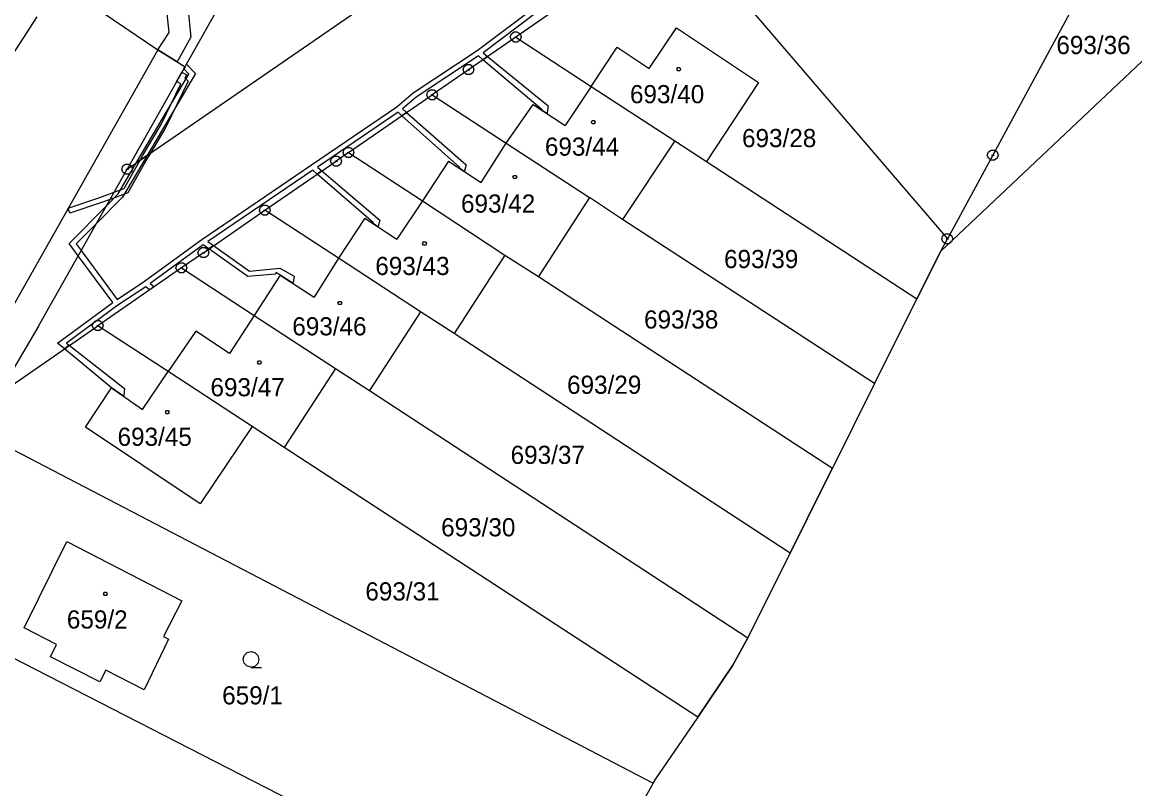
# Model space of a CAD drawing. Extents: x -759699 to -757730, y -1172308 to -1170857.
# Drawn here: x -758375.4 to -758271.3, y -1171278.3 to -1171206.6 of the extents above; entities that cross this region are included whole.
import ezdxf

# ---------------------------------------------------------------- set-up
doc = ezdxf.new("R2010")
doc.units = 0
for name, color, linetype in [('Vrstva 1', 7, 'Continuous'), ('Vrstva 11', 7, 'Continuous'), ('Vrstva 12', 7, 'Continuous'), ('Vrstva 13', 7, 'Continuous'), ('Vrstva 2', 7, 'Continuous'), ('Vrstva 3', 7, 'Continuous'), ('Vrstva 4', 7, 'Continuous'), ('Vrstva 5', 7, 'Continuous'), ('Vrstva 8', 7, 'Continuous')]:
    doc.layers.add(name, color=color, linetype=linetype)

msp = doc.modelspace()

# ---------------------------------------------------------------- linework, layer by layer
at = {"layer": 'Vrstva 1'}
for p, q in [((-758386.86, -1171192.81), (-758362.75, -1171209.16)), ((-758365.62, -1171220.33), (-758328.98, -1171195.04)), ((-758274.38, -1171200.21), (-758284.58, -1171219.02)), ((-758360.06, -1171210.49), (-758355.37, -1171202.2)), ((-758323.19, -1171203.79), (-758329.24, -1171207.97)), ((-758306.89, -1171205.79), (-758288.83, -1171226.85)), ((-758374.07, -1171206.07), (-758380.71, -1171216.2)), ((-758316.74, -1171210.9), (-758314.19, -1171207.09)), ((-758314.19, -1171207.09), (-758306.51, -1171212.22)), ((-758329.24, -1171207.97), (-758333.65, -1171211.02)), ((-758329.24, -1171207.97), (-758322.18, -1171212.58)), ((-758289.45, -1171228), (-758267.94, -1171207.71)), ((-758362.75, -1171209.16), (-758376.54, -1171233.55)), ((-758362.75, -1171209.16), (-758360.2, -1171210.74)), ((-758322.18, -1171212.58), (-758319.73, -1171208.9)), ((-758319.73, -1171208.9), (-758316.74, -1171210.9)), ((-758360.32, -1171210.95), (-758365.62, -1171220.33)), ((-758360.2, -1171210.74), (-758360.32, -1171210.95)), ((-758360.2, -1171210.74), (-758360.06, -1171210.49)), ((-758333.65, -1171211.02), (-758337.06, -1171213.37)), ((-758306.51, -1171212.22), (-758311.37, -1171219.62)), ((-758322.18, -1171212.58), (-758314.33, -1171217.69)), ((-758344.89, -1171218.77), (-758337.06, -1171213.37)), ((-758337.06, -1171213.37), (-758330.12, -1171217.9)), ((-758330.12, -1171217.9), (-758322.34, -1171222.98)), ((-758314.33, -1171217.69), (-758319.23, -1171225.03)), ((-758314.33, -1171217.69), (-758311.37, -1171219.62)), ((-758352.72, -1171224.17), (-758346.06, -1171219.58)), ((-758344.89, -1171218.77), (-758346.06, -1171219.58)), ((-758344.89, -1171218.77), (-758337.98, -1171223.28)), ((-758284.58, -1171219.02), (-758288.83, -1171226.85)), ((-758373.93, -1171235.02), (-758365.62, -1171220.33)), ((-758311.37, -1171219.62), (-758291.68, -1171232.47)), ((-758337.98, -1171223.28), (-758330.25, -1171228.37)), ((-758322.34, -1171222.98), (-758327.12, -1171230.37)), ((-758319.23, -1171225.03), (-758322.34, -1171222.98)), ((-758358.48, -1171228.15), (-758352.72, -1171224.17)), ((-758345.82, -1171228.67), (-758352.72, -1171224.17)), ((-758295.64, -1171240.4), (-758319.23, -1171225.03)), ((-758289.45, -1171228), (-758288.83, -1171226.85)), ((-758358.48, -1171228.15), (-758360.54, -1171229.57)), ((-758338.14, -1171233.68), (-758345.82, -1171228.67)), ((-758330.25, -1171228.37), (-758335.01, -1171235.72)), ((-758330.25, -1171228.37), (-758327.12, -1171230.37)), ((-758291.68, -1171232.47), (-758289.45, -1171228)), ((-758360.54, -1171229.57), (-758368.37, -1171234.98)), ((-758360.54, -1171229.57), (-758353.72, -1171234.02)), ((-758327.12, -1171230.37), (-758299.59, -1171248.33)), ((-758292.58, -1171234.27), (-758291.68, -1171232.47)), ((-758353.72, -1171234.02), (-758346.1, -1171238.99)), ((-758338.14, -1171233.68), (-758342.93, -1171241.06)), ((-758335.01, -1171235.72), (-758338.14, -1171233.68)), ((-758377.73, -1171241.44), (-758368.37, -1171234.98)), ((-758373.93, -1171235.02), (-758377.73, -1171241.44)), ((-758361.79, -1171239.27), (-758368.37, -1171234.98)), ((-758295.64, -1171240.4), (-758292.58, -1171234.27)), ((-758303.54, -1171256.26), (-758335.01, -1171235.72)), ((-758364.19, -1171242.83), (-758361.79, -1171239.27)), ((-758353.9, -1171244.42), (-758361.79, -1171239.27)), ((-758346.1, -1171238.99), (-758350.91, -1171246.37)), ((-758346.1, -1171238.99), (-758342.93, -1171241.06)), ((-758295.64, -1171240.4), (-758299.59, -1171248.33)), ((-758369.53, -1171244.48), (-758367.09, -1171240.79)), ((-758367.09, -1171240.79), (-758364.19, -1171242.83)), ((-758342.93, -1171241.06), (-758307.5, -1171264.19)), ((-758358.79, -1171251.66), (-758369.53, -1171244.48)), ((-758353.9, -1171244.42), (-758358.79, -1171251.66)), ((-758350.91, -1171246.37), (-758353.9, -1171244.42)), ((-758379.62, -1171244.86), (-758316.38, -1171277.79)), ((-758312.19, -1171271.63), (-758350.91, -1171246.37)), ((-758300.32, -1171249.8), (-758299.59, -1171248.33)), ((-758303.54, -1171256.26), (-758300.32, -1171249.8)), ((-758375.27, -1171263.26), (-758371.28, -1171255.17)), ((-758371.28, -1171255.17), (-758360.49, -1171260.74)), ((-758307.5, -1171264.19), (-758303.54, -1171256.26)), ((-758387.5, -1171260.32), (-758324.71, -1171292.52)), ((-758360.49, -1171260.74), (-758362.21, -1171264.08)), ((-758372.24, -1171264.83), (-758375.27, -1171263.26)), ((-758361.76, -1171264.31), (-758364.03, -1171269.07)), ((-758362.21, -1171264.08), (-758361.76, -1171264.31)), ((-758308.92, -1171266.75), (-758307.5, -1171264.19)), ((-758372.8, -1171265.97), (-758372.24, -1171264.83)), ((-758368.18, -1171268.33), (-758372.8, -1171265.97)), ((-758367.61, -1171267.22), (-758368.18, -1171268.33)), ((-758364.03, -1171269.07), (-758367.61, -1171267.22)), ((-758312.19, -1171271.63), (-758308.92, -1171266.75)), ((-758312.19, -1171271.63), (-758316.16, -1171277.4)), ((-758316.38, -1171277.79), (-758317.68, -1171280.14)), ((-758316.38, -1171277.79), (-758316.16, -1171277.4))]:
    msp.add_line(p, q, dxfattribs=at)
at = {"layer": 'Vrstva 11'}
for p, q in [((-758267.94, -1171207.71), (-758289.45, -1171228)), ((-758289.45, -1171228), (-758291.68, -1171232.47)), ((-758291.68, -1171232.47), (-758292.58, -1171234.27)), ((-758292.58, -1171234.27), (-758295.64, -1171240.4)), ((-758295.64, -1171240.4), (-758299.59, -1171248.33)), ((-758299.59, -1171248.33), (-758300.32, -1171249.8)), ((-758300.32, -1171249.8), (-758303.54, -1171256.26)), ((-758303.54, -1171256.26), (-758307.5, -1171264.19)), ((-758307.5, -1171264.19), (-758308.92, -1171266.75)), ((-758308.92, -1171266.75), (-758312.19, -1171271.63)), ((-758312.19, -1171271.63), (-758316.16, -1171277.4)), ((-758316.38, -1171277.79), (-758317.68, -1171280.14)), ((-758316.16, -1171277.4), (-758316.38, -1171277.79))]:
    msp.add_line(p, q, dxfattribs=at)
at = {"layer": 'Vrstva 12'}
for p, q in [((-758374.07, -1171206.07), (-758380.71, -1171216.2)), ((-758316.74, -1171210.9), (-758314.19, -1171207.09)), ((-758314.19, -1171207.09), (-758306.51, -1171212.22)), ((-758322.18, -1171212.58), (-758319.73, -1171208.9)), ((-758319.73, -1171208.9), (-758316.74, -1171210.9)), ((-758306.51, -1171212.22), (-758311.37, -1171219.62)), ((-758322.18, -1171212.58), (-758324.62, -1171216.25)), ((-758322.18, -1171212.58), (-758314.33, -1171217.69)), ((-758322.18, -1171212.58), (-758314.33, -1171217.69)), ((-758330.12, -1171217.9), (-758327.6, -1171214.27)), ((-758327.6, -1171214.27), (-758324.62, -1171216.25)), ((-758332.47, -1171221.59), (-758330.12, -1171217.9)), ((-758330.12, -1171217.9), (-758322.34, -1171222.98)), ((-758330.12, -1171217.9), (-758322.34, -1171222.98)), ((-758314.33, -1171217.69), (-758319.23, -1171225.03)), ((-758314.33, -1171217.69), (-758311.37, -1171219.62)), ((-758335.52, -1171219.58), (-758337.98, -1171223.28)), ((-758335.52, -1171219.58), (-758332.47, -1171221.59)), ((-758337.98, -1171223.28), (-758340.38, -1171226.89)), ((-758337.98, -1171223.28), (-758330.25, -1171228.37)), ((-758337.98, -1171223.28), (-758330.25, -1171228.37)), ((-758322.34, -1171222.98), (-758327.12, -1171230.37)), ((-758319.23, -1171225.03), (-758322.34, -1171222.98)), ((-758343.38, -1171224.91), (-758345.82, -1171228.67)), ((-758343.38, -1171224.91), (-758340.38, -1171226.89)), ((-758345.82, -1171228.67), (-758348.11, -1171232.3)), ((-758338.14, -1171233.68), (-758345.82, -1171228.67)), ((-758338.14, -1171233.68), (-758345.82, -1171228.67)), ((-758330.25, -1171228.37), (-758335.01, -1171235.72)), ((-758330.25, -1171228.37), (-758327.12, -1171230.37)), ((-758351.28, -1171230.25), (-758353.72, -1171234.02)), ((-758351.28, -1171230.25), (-758348.11, -1171232.3)), ((-758353.72, -1171234.02), (-758356.03, -1171237.57)), ((-758353.72, -1171234.02), (-758346.1, -1171238.99)), ((-758353.72, -1171234.02), (-758346.1, -1171238.99)), ((-758338.14, -1171233.68), (-758342.93, -1171241.06)), ((-758335.01, -1171235.72), (-758338.14, -1171233.68)), ((-758359.2, -1171235.51), (-758361.79, -1171239.27)), ((-758356.03, -1171237.57), (-758359.2, -1171235.51)), ((-758364.19, -1171242.83), (-758361.79, -1171239.27)), ((-758353.9, -1171244.42), (-758361.79, -1171239.27)), ((-758353.9, -1171244.42), (-758361.79, -1171239.27)), ((-758346.1, -1171238.99), (-758350.91, -1171246.37)), ((-758346.1, -1171238.99), (-758342.93, -1171241.06)), ((-758369.53, -1171244.48), (-758367.09, -1171240.79)), ((-758367.09, -1171240.79), (-758364.19, -1171242.83)), ((-758358.79, -1171251.66), (-758369.53, -1171244.48)), ((-758353.9, -1171244.42), (-758358.79, -1171251.66)), ((-758350.91, -1171246.37), (-758353.9, -1171244.42)), ((-758375.27, -1171263.26), (-758371.28, -1171255.17)), ((-758371.28, -1171255.17), (-758360.49, -1171260.74)), ((-758360.49, -1171260.74), (-758362.21, -1171264.08)), ((-758372.24, -1171264.83), (-758375.27, -1171263.26)), ((-758361.76, -1171264.31), (-758364.03, -1171269.07)), ((-758362.21, -1171264.08), (-758361.76, -1171264.31)), ((-758372.8, -1171265.97), (-758372.24, -1171264.83)), ((-758368.18, -1171268.33), (-758372.8, -1171265.97)), ((-758367.61, -1171267.22), (-758368.18, -1171268.33)), ((-758364.03, -1171269.07), (-758367.61, -1171267.22))]:
    msp.add_line(p, q, dxfattribs=at)
at = {"layer": 'Vrstva 13'}
for p, q in [((-758361.7, -1171207.55), (-758362.65, -1171198.06)), ((-758360.52, -1171199.28), (-758359.65, -1171207.98)), ((-758332.85, -1171209.22), (-758323.01, -1171201.81)), ((-758322.9, -1171202.36), (-758332.3, -1171209.43)), ((-758362.75, -1171209.16), (-758361.7, -1171207.55)), ((-758359.65, -1171207.98), (-758360.94, -1171210.28)), ((-758360.94, -1171210.28), (-758362.75, -1171209.16)), ((-758338.85, -1171213.18), (-758332.85, -1171209.22)), ((-758332.73, -1171209.73), (-758338.55, -1171213.58)), ((-758332.31, -1171210.09), (-758332.73, -1171209.73)), ((-758331.87, -1171209.78), (-758332.31, -1171210.09)), ((-758332.31, -1171210.09), (-758331.87, -1171209.78)), ((-758326.76, -1171214.77), (-758332.31, -1171210.09)), ((-758332.3, -1171209.43), (-758331.87, -1171209.78)), ((-758331.87, -1171209.78), (-758326.19, -1171214.41)), ((-758360.99, -1171212.13), (-758360.49, -1171211.26)), ((-758360.49, -1171211.26), (-758360.06, -1171211.5)), ((-758360.32, -1171210.95), (-758360.2, -1171210.74)), ((-758359.84, -1171211.45), (-758360.32, -1171210.95)), ((-758360.2, -1171210.74), (-758360.06, -1171210.49)), ((-758360.06, -1171210.49), (-758359.22, -1171211.37)), ((-758364.73, -1171219.72), (-758359.84, -1171211.45)), ((-758359.22, -1171211.37), (-758363.76, -1171219.04)), ((-758359.92, -1171212.08), (-758361.99, -1171216.4)), ((-758360.6, -1171212.34), (-758360.99, -1171212.13)), ((-758360.06, -1171211.5), (-758360.23, -1171211.8)), ((-758360.23, -1171211.8), (-758359.92, -1171212.08)), ((-758362.43, -1171216.16), (-758360.6, -1171212.34)), ((-758340.38, -1171214.49), (-758338.85, -1171213.18)), ((-758338.55, -1171213.58), (-758339.85, -1171214.69)), ((-758348.35, -1171219.92), (-758340.38, -1171214.49)), ((-758340.25, -1171215.01), (-758347.8, -1171220.15)), ((-758339.9, -1171215.33), (-758340.25, -1171215.01)), ((-758339.46, -1171215.03), (-758339.9, -1171215.33)), ((-758339.9, -1171215.33), (-758339.46, -1171215.03)), ((-758334.48, -1171220.19), (-758339.9, -1171215.33)), ((-758339.85, -1171214.69), (-758339.46, -1171215.03)), ((-758339.46, -1171215.03), (-758333.87, -1171219.92)), ((-758326.79, -1171214.81), (-758326.76, -1171214.77)), ((-758326.32, -1171215.12), (-758326.79, -1171214.81)), ((-758326.31, -1171215.07), (-758326.32, -1171215.12)), ((-758326.19, -1171214.41), (-758326.31, -1171215.07)), ((-758364.18, -1171219.08), (-758362.43, -1171216.16)), ((-758361.99, -1171216.4), (-758363.44, -1171218.82)), ((-758363.76, -1171219.04), (-758366.06, -1171222.94)), ((-758365.91, -1171222.14), (-758364.41, -1171219.49)), ((-758363.74, -1171219.34), (-758365.57, -1171222.54)), ((-758363.76, -1171219.04), (-758364.73, -1171219.72)), ((-758364.73, -1171219.72), (-758363.76, -1171219.04)), ((-758363.44, -1171218.82), (-758364.41, -1171219.49)), ((-758364.41, -1171219.49), (-758363.44, -1171218.82)), ((-758364.41, -1171219.49), (-758364.18, -1171219.08)), ((-758363.44, -1171218.82), (-758363.74, -1171219.34)), ((-758366.46, -1171222.64), (-758364.73, -1171219.72)), ((-758358.63, -1171226.91), (-758348.35, -1171219.92)), ((-758348.23, -1171220.44), (-758358.05, -1171227.11)), ((-758347.82, -1171220.79), (-758348.23, -1171220.44)), ((-758347.82, -1171220.79), (-758347.39, -1171220.5)), ((-758347.39, -1171220.5), (-758347.82, -1171220.79)), ((-758347.8, -1171220.15), (-758347.39, -1171220.5)), ((-758347.39, -1171220.5), (-758341.95, -1171225.1)), ((-758334.51, -1171220.24), (-758334.48, -1171220.19)), ((-758334.07, -1171220.54), (-758334.51, -1171220.24)), ((-758334.05, -1171220.48), (-758334.07, -1171220.54)), ((-758333.87, -1171219.92), (-758334.05, -1171220.48)), ((-758342.56, -1171225.37), (-758347.82, -1171220.79)), ((-758368.17, -1171222.98), (-758366.84, -1171222.48)), ((-758367.56, -1171223.75), (-758366.46, -1171222.64)), ((-758365.57, -1171222.54), (-758367.22, -1171223.16)), ((-758366.84, -1171222.48), (-758365.91, -1171222.14)), ((-758371.13, -1171223.99), (-758368.17, -1171222.98)), ((-758371.04, -1171227.29), (-758367.56, -1171223.75)), ((-758368.01, -1171223.46), (-758370.97, -1171224.46)), ((-758366.06, -1171222.94), (-758368.5, -1171225.42)), ((-758367.22, -1171223.16), (-758368.01, -1171223.46)), ((-758370.97, -1171224.46), (-758371.13, -1171223.99)), ((-758368.5, -1171225.42), (-758370.38, -1171227.33)), ((-758342.6, -1171225.43), (-758342.56, -1171225.37)), ((-758342.15, -1171225.72), (-758342.6, -1171225.43)), ((-758342.13, -1171225.66), (-758342.15, -1171225.72)), ((-758341.95, -1171225.1), (-758342.13, -1171225.66)), ((-758370.2, -1171228.43), (-758371.04, -1171227.29)), ((-758370.38, -1171227.33), (-758369.93, -1171227.95)), ((-758364, -1171230.82), (-758358.63, -1171226.91)), ((-758358.49, -1171227.42), (-758363.45, -1171231.04)), ((-758357.97, -1171227.79), (-758358.49, -1171227.42)), ((-758358.05, -1171227.11), (-758357.52, -1171227.49)), ((-758357.97, -1171227.79), (-758357.52, -1171227.49)), ((-758357.52, -1171227.49), (-758357.97, -1171227.79)), ((-758354.32, -1171230.39), (-758357.97, -1171227.79)), ((-758357.52, -1171227.49), (-758354.18, -1171229.87)), ((-758366.97, -1171232.82), (-758370.2, -1171228.43)), ((-758369.93, -1171227.95), (-758366.56, -1171232.53)), ((-758354.18, -1171229.87), (-758351.34, -1171229.6)), ((-758351.67, -1171230), (-758351.76, -1171230.15)), ((-758351.28, -1171230.25), (-758351.67, -1171230)), ((-758351.34, -1171229.6), (-758349.97, -1171230.34)), ((-758366.56, -1171232.53), (-758364, -1171230.82)), ((-758363.45, -1171231.04), (-758363.09, -1171231.33)), ((-758351.76, -1171230.15), (-758354.32, -1171230.39)), ((-758350.11, -1171231.01), (-758351.28, -1171230.25)), ((-758350.09, -1171230.93), (-758350.11, -1171231.01)), ((-758349.97, -1171230.34), (-758350.09, -1171230.93)), ((-758363.87, -1171231.34), (-758366.48, -1171233.07)), ((-758363.52, -1171231.63), (-758363.87, -1171231.34)), ((-758363.09, -1171231.33), (-758363.52, -1171231.63)), ((-758372.13, -1171236.61), (-758366.97, -1171232.82)), ((-758366.48, -1171233.07), (-758371.31, -1171236.61)), ((-758371.49, -1171237.14), (-758372.13, -1171236.61)), ((-758371.49, -1171237.14), (-758371.04, -1171236.82)), ((-758371.04, -1171236.82), (-758371.49, -1171237.14)), ((-758367.09, -1171240.79), (-758371.49, -1171237.14)), ((-758371.31, -1171236.61), (-758371.04, -1171236.82)), ((-758371.04, -1171236.82), (-758365.88, -1171240.87)), ((-758365.95, -1171241.59), (-758367.09, -1171240.79)), ((-758365.88, -1171240.87), (-758365.94, -1171241.5)), ((-758365.94, -1171241.5), (-758365.95, -1171241.59))]:
    msp.add_line(p, q, dxfattribs=at)
at = {"layer": 'Vrstva 3'}
msp.add_lwpolyline([(-758354.01, -1171266.95), (-758354.39, -1171266.85), (-758354.66, -1171266.58), (-758354.76, -1171266.21), (-758354.66, -1171265.84), (-758354.39, -1171265.57), (-758354.02, -1171265.47), (-758353.65, -1171265.57), (-758353.38, -1171265.84), (-758353.28, -1171266.22), (-758353.38, -1171266.6), (-758353.65, -1171266.87), (-758354.03, -1171266.97), (-758353.03, -1171266.97)], dxfattribs=at)
at = {"layer": 'Vrstva 4'}
for p, q in [((-758322.18, -1171212.58), (-758324.62, -1171216.25)), ((-758330.12, -1171217.9), (-758327.6, -1171214.27)), ((-758327.6, -1171214.27), (-758324.62, -1171216.25)), ((-758332.47, -1171221.59), (-758330.12, -1171217.9)), ((-758335.52, -1171219.58), (-758337.98, -1171223.28)), ((-758335.52, -1171219.58), (-758332.47, -1171221.59)), ((-758337.98, -1171223.28), (-758340.38, -1171226.89)), ((-758343.38, -1171224.91), (-758345.82, -1171228.67)), ((-758343.38, -1171224.91), (-758340.38, -1171226.89)), ((-758345.82, -1171228.67), (-758348.11, -1171232.3)), ((-758351.28, -1171230.25), (-758353.72, -1171234.02)), ((-758351.28, -1171230.25), (-758348.11, -1171232.3)), ((-758353.72, -1171234.02), (-758356.03, -1171237.57)), ((-758359.2, -1171235.51), (-758361.79, -1171239.27)), ((-758356.03, -1171237.57), (-758359.2, -1171235.51))]:
    msp.add_line(p, q, dxfattribs=at)
at = {"layer": 'Vrstva 5'}
for points in [[(-758313.89, -1171210.83), (-758313.8, -1171210.98), (-758313.89, -1171211.13), (-758314.07, -1171211.13), (-758314.16, -1171210.98), (-758314.07, -1171210.83)], [(-758321.89, -1171215.78), (-758321.8, -1171215.93), (-758321.89, -1171216.08), (-758322.07, -1171216.08), (-758322.16, -1171215.93), (-758322.07, -1171215.78)], [(-758329.23, -1171220.92), (-758329.14, -1171221.07), (-758329.23, -1171221.22), (-758329.41, -1171221.22), (-758329.5, -1171221.07), (-758329.41, -1171220.92)], [(-758337.69, -1171227.14), (-758337.6, -1171227.29), (-758337.69, -1171227.44), (-758337.87, -1171227.44), (-758337.96, -1171227.29), (-758337.87, -1171227.14)], [(-758345.62, -1171232.71), (-758345.53, -1171232.86), (-758345.62, -1171233.01), (-758345.8, -1171233.01), (-758345.89, -1171232.86), (-758345.8, -1171232.71)], [(-758353.15, -1171238.28), (-758353.06, -1171238.43), (-758353.15, -1171238.58), (-758353.33, -1171238.58), (-758353.42, -1171238.43), (-758353.33, -1171238.28)], [(-758361.77, -1171242.93), (-758361.68, -1171243.08), (-758361.77, -1171243.23), (-758361.95, -1171243.23), (-758362.04, -1171243.08), (-758361.95, -1171242.93)], [(-758367.57, -1171259.94), (-758367.48, -1171260.09), (-758367.57, -1171260.24), (-758367.75, -1171260.24), (-758367.84, -1171260.09), (-758367.75, -1171259.94)]]:
    msp.add_lwpolyline(points, close=True, dxfattribs=at)
at = {"layer": 'Vrstva 8'}
for p, q in [((-758329.36, -1171207.97), (-758329.12, -1171207.97)), ((-758333.77, -1171211.02), (-758333.53, -1171211.02)), ((-758337.18, -1171213.37), (-758336.94, -1171213.37)), ((-758346.18, -1171219.58), (-758345.94, -1171219.58)), ((-758345.01, -1171218.77), (-758344.77, -1171218.77)), ((-758284.7, -1171219.02), (-758284.46, -1171219.02)), ((-758365.74, -1171220.33), (-758365.5, -1171220.33)), ((-758352.84, -1171224.17), (-758352.6, -1171224.17)), ((-758288.95, -1171226.85), (-758288.71, -1171226.85)), ((-758358.6, -1171228.15), (-758358.36, -1171228.15)), ((-758360.66, -1171229.57), (-758360.42, -1171229.57)), ((-758368.49, -1171234.98), (-758368.25, -1171234.98))]:
    msp.add_line(p, q, dxfattribs=at)
for points in [[(-758329.09, -1171207.49), (-758328.84, -1171207.67), (-758328.74, -1171207.96), (-758328.84, -1171208.25), (-758329.09, -1171208.43), (-758329.4, -1171208.43), (-758329.65, -1171208.25), (-758329.75, -1171207.96), (-758329.65, -1171207.67), (-758329.4, -1171207.49)], [(-758333.5, -1171210.54), (-758333.25, -1171210.72), (-758333.15, -1171211.01), (-758333.25, -1171211.3), (-758333.5, -1171211.48), (-758333.81, -1171211.48), (-758334.06, -1171211.3), (-758334.16, -1171211.01), (-758334.06, -1171210.72), (-758333.81, -1171210.54)], [(-758336.91, -1171212.89), (-758336.66, -1171213.07), (-758336.56, -1171213.36), (-758336.66, -1171213.65), (-758336.91, -1171213.83), (-758337.22, -1171213.83), (-758337.47, -1171213.65), (-758337.57, -1171213.36), (-758337.47, -1171213.07), (-758337.22, -1171212.89)], [(-758344.74, -1171218.29), (-758344.49, -1171218.47), (-758344.39, -1171218.76), (-758344.49, -1171219.05), (-758344.74, -1171219.23), (-758345.05, -1171219.23), (-758345.3, -1171219.05), (-758345.4, -1171218.76), (-758345.3, -1171218.47), (-758345.05, -1171218.29)], [(-758284.43, -1171218.54), (-758284.18, -1171218.72), (-758284.08, -1171219.01), (-758284.18, -1171219.3), (-758284.43, -1171219.48), (-758284.74, -1171219.48), (-758284.99, -1171219.3), (-758285.09, -1171219.01), (-758284.99, -1171218.72), (-758284.74, -1171218.54)], [(-758345.91, -1171219.1), (-758345.66, -1171219.28), (-758345.56, -1171219.57), (-758345.66, -1171219.86), (-758345.91, -1171220.04), (-758346.22, -1171220.04), (-758346.47, -1171219.86), (-758346.57, -1171219.57), (-758346.47, -1171219.28), (-758346.22, -1171219.1)], [(-758365.47, -1171219.85), (-758365.22, -1171220.03), (-758365.12, -1171220.32), (-758365.22, -1171220.61), (-758365.47, -1171220.79), (-758365.78, -1171220.79), (-758366.03, -1171220.61), (-758366.13, -1171220.32), (-758366.03, -1171220.03), (-758365.78, -1171219.85)], [(-758352.57, -1171223.69), (-758352.32, -1171223.87), (-758352.22, -1171224.16), (-758352.32, -1171224.45), (-758352.57, -1171224.63), (-758352.88, -1171224.63), (-758353.13, -1171224.45), (-758353.23, -1171224.16), (-758353.13, -1171223.87), (-758352.88, -1171223.69)], [(-758288.68, -1171226.37), (-758288.43, -1171226.55), (-758288.33, -1171226.84), (-758288.43, -1171227.13), (-758288.68, -1171227.31), (-758288.99, -1171227.31), (-758289.24, -1171227.13), (-758289.34, -1171226.84), (-758289.24, -1171226.55), (-758288.99, -1171226.37)], [(-758358.33, -1171227.67), (-758358.08, -1171227.85), (-758357.98, -1171228.14), (-758358.08, -1171228.43), (-758358.33, -1171228.61), (-758358.64, -1171228.61), (-758358.89, -1171228.43), (-758358.99, -1171228.14), (-758358.89, -1171227.85), (-758358.64, -1171227.67)], [(-758360.39, -1171229.09), (-758360.14, -1171229.27), (-758360.04, -1171229.56), (-758360.14, -1171229.85), (-758360.39, -1171230.03), (-758360.7, -1171230.03), (-758360.95, -1171229.85), (-758361.05, -1171229.56), (-758360.95, -1171229.27), (-758360.7, -1171229.09)], [(-758368.22, -1171234.5), (-758367.97, -1171234.68), (-758367.87, -1171234.97), (-758367.97, -1171235.26), (-758368.22, -1171235.44), (-758368.53, -1171235.44), (-758368.78, -1171235.26), (-758368.88, -1171234.97), (-758368.78, -1171234.68), (-758368.53, -1171234.5)]]:
    msp.add_lwpolyline(points, close=True, dxfattribs=at)

# ---------------------------------------------------------------- texts
at = {"layer": 'Vrstva 2'}
for s, p in [('693/36', (-758278.626, -1171209.56)), ('693/40', (-758318.546, -1171214.16)), ('693/44', (-758326.509, -1171219.07)), ('693/28', (-758308.053, -1171218.27)), ('693/42', (-758334.363, -1171224.4)), ('693/39', (-758309.736, -1171229.59)), ('693/43', (-758342.386, -1171230.24)), ('693/46', (-758350.159, -1171235.89)), ('693/38', (-758317.227, -1171235.25)), ('693/47', (-758357.819, -1171241.59)), ('693/29', (-758324.433, -1171241.36)), ('693/45', (-758366.516, -1171246.23)), ('693/37', (-758329.716, -1171247.92)), ('693/30', (-758336.223, -1171254.7)), ('693/31', (-758343.318, -1171260.7)), ('659/2', (-758371.264, -1171263.33)), ('659/1', (-758356.722, -1171270.43))]:
    msp.add_text(s, height=1.7, dxfattribs=at).set_placement(p)

doc.saveas('drawing.dxf')
